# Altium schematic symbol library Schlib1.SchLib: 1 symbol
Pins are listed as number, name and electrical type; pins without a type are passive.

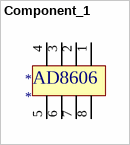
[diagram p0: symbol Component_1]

## Component_1
designator *
footprint MSOP-8 (TSOP, 8-Leads, Body 3x3mm, Pitch 0.65mm, IPC Low Density)
pins: 1 (power), 2 (power), 3 (power), 4 (power), 5 (power), 6 (power), 7 (power), 8 (power)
